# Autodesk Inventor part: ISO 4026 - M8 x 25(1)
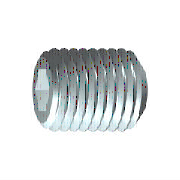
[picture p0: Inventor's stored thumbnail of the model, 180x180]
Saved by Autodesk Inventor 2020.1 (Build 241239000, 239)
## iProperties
Created: 2019-01
Part Number: ISO 4026 - M8 x 25(1)
Material: Edelstahl, 440C
Description: Innensechskant-Gewindestifte mit Kegelstumpf
Document SubType Name: Modeling
Standard: ISO 4026
Designer: lutzd
Standard Revision: Third edition 2003-12-01
Standards Organization: ISO
Language: de-DE
Size Designation: M8 x 25
Categories: <MemberInstance><Categories><Category DisplayName="Verbindungselemente" InternalName="e4da775c-781d-43d5-af7c-5136215cf5a6" Mnemonic="FSTN"><Category DisplayNam
Mass: 9.03866 g
Surface Area: 7.77792 cm^2
Volume: 1.16628 cm^3
Density: 7.75 g/cm^3
Appearance: Semi-Polished(3)
IsCustomPart: 0
Author: lutzd
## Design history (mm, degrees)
sketch "Skizze1"
  geometry: L1 (0, 0)-(18.667, 0); L2 (25, 2.309)-(25, 4); L3 (25, 4)-(0, 4); L4 (25, 2.309)-(20, 2.309); L5 (20, 2.309)-(18.667, 0); L6 (0, -0.8)-(0, 4.8) reference; L7 (0, 4)-(0, 0)
  constraints: 13 end point, 3 parallel, 1 collinear, 1 perpendicular, 1 point on line
  dimensions: "d0" = 5 distance of L2.start L4.end (= INTI); "d1" = 60 deg angle of L5 L1; "d2" = 8 diameter of L3 L1 (= NND); "d3" = 4.6188 diameter of L4 L1 (= 1.1547 x SW); "d5" = 25 distance from line of L2 L3.end (= NLG)
revolve "Körper" sketch "Skizze1" stored, may be unused: angle "d6" = 90 deg
sketch "Skizze2"
  geometry: L1 (-1.155, 2)-(1.155, 2); L2 (1.155, 2)-(2.309, 0); L3 (2.309, 0)-(1.155, -2); L4 (1.155, -2)-(-1.155, -2); L5 (-1.155, -2)-(-2.309, 0); L6 (-2.309, 0)-(-1.155, 2); A1 r 2.309 centre (0, 0) between (-1.155, 2) and (1.155, 2) reference; 2 further points
  constraints: 12 end point, 2 point on circle, 1 coincident, 1 horizontal, 11 other
extrude "Loch" join sketch "Skizze2" taper "d9" = 0 deg; stored distance "d21" = 10
workaxis "Work Axis1"
workplane "Work Plane1"
body "Solid1"
chamfer "Fase1" distance "d7" = 0.76681 (= -0.5 x GD1 + 0.5 x NND); stored, may be unused: angle "d8" = 45 deg (= FAWI), second distance "d29" = 0.76681 (= -0.5 x GD1 + 0.5 x NND)
feature "Gewinde" dims "d11" = 25 (= NLG), "d12" = 0
chamfer "Fase2" distance "d13" = 0.76681 (= -0.5 x GD1 + 0.5 x NND); stored, may be unused: angle "d14" = 45 deg (= FAWI), second distance "d30" = 0.76681 (= -0.5 x GD1 + 0.5 x NND)
other parameters: "NND" = 8 [user parameter; used in 5 equation terms], "NLG" = 25 [user parameter; used in 2 equation terms], "INTI" = 5 [user parameter; used in 1 equation term], "FAWI" = 45 deg [user parameter; used in 2 equation terms], "SW" = 4 [user parameter; used in 2 equation terms], "GD1" = 6.46637 (= THREADDIA - 1.2269 x PTC) [user parameter; used in 4 equation terms], "d4" = 0, "FAWI1" = 45 deg [user parameter], "d15" = 0, "d31" = 0, "GUL" = 0.76681 (= 0.61345 x PTC) [user parameter], "SPD" = 5.5 [user parameter], "SEWI" = 90 deg [user parameter], "TOA" = 30 deg [user parameter], "THREADDIA" = 8 [user parameter; used in 1 equation term], "TPU" = 8 (computed from PTC) [user parameter], "PTC" = 1.25 [user parameter; used in 4 equation terms], "GAL" = 0.76681 (= 0.61345 x PTC) [user parameter], "E0" = 4.62 (= 1.155 x SW) [user parameter]
